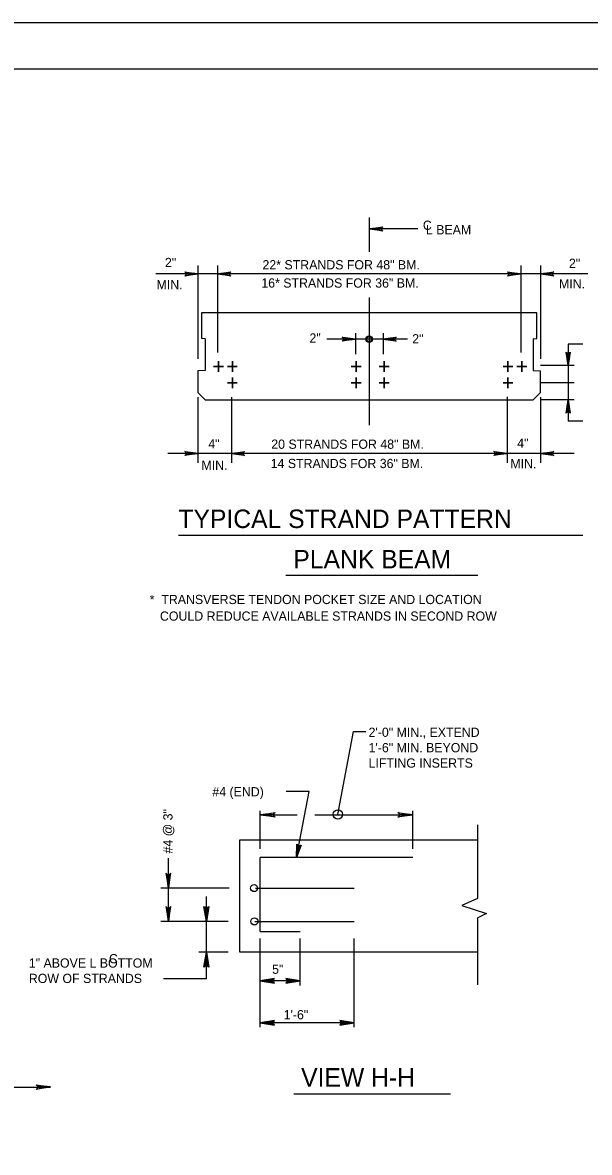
# Model space of a CAD drawing. Extents: x 639331 to 643089, y 299088 to 300975.
# Drawn here: x 642553.9 to 642738.1, y 300502.8 to 300869.7 of the extents above; entities that cross this region are included whole.
import ezdxf

# ---------------------------------------------------------------- set-up
doc = ezdxf.new("R2010")
doc.units = 0
doc.layers.add('1', color=7, linetype='Continuous')
doc.layers.add('PLT-BNDY', color=7, linetype='Continuous')

msp = doc.modelspace()

# ---------------------------------------------------------------- linework, layer by layer
at = {"layer": '1'}
for p, q in [((642274.06, 300854.66), (643060.06, 300854.66)), ((642666.55, 300806.4), (642666.55, 300795.18)), ((642682.33, 300802.64), (642666.7, 300802.64)), ((642617.31, 300788.03), (642597.21, 300788.03)), ((642610.9, 300790.75), (642610.9, 300760.45)), ((642617.31, 300790.75), (642617.31, 300762.54)), ((642715.79, 300788.03), (642617.31, 300788.03)), ((642715.79, 300790.75), (642715.79, 300762.54)), ((642737.64, 300788.03), (642715.79, 300788.03)), ((642722.2, 300790.75), (642722.2, 300760.45)), ((642666.55, 300780.44), (642666.55, 300738.9)), ((642721, 300775.37), (642612.1, 300775.37)), ((642612.1, 300775.37), (642612.1, 300767.13)), ((642721, 300767.13), (642721, 300775.37)), ((642613.3, 300766.98), (642612.1, 300767.13)), ((642613.3, 300766.98), (642613.3, 300756.71)), ((642662.05, 300766.87), (642652.84, 300766.87)), ((642662.05, 300768.85), (642662.05, 300761.94)), ((642671.05, 300766.87), (642662.05, 300766.87)), ((642671.05, 300768.85), (642671.05, 300761.94)), ((642679.04, 300766.87), (642671.05, 300766.87)), ((642719.8, 300766.98), (642721, 300767.13)), ((642719.8, 300766.98), (642719.8, 300756.71)), ((642731.21, 300765.26), (642731.21, 300758.34)), ((642735.94, 300765.26), (642731.21, 300765.26)), ((642733.19, 300758.34), (642722.2, 300758.34)), ((642731.21, 300758.34), (642731.21, 300747.17)), ((642613.3, 300756.71), (642610.9, 300756.56)), ((642610.9, 300756.56), (642610.9, 300749.57)), ((642719.8, 300756.71), (642722.2, 300756.56)), ((642722.2, 300749.57), (642722.2, 300756.56)), ((642733.19, 300752.64), (642722.2, 300752.64)), ((642610.9, 300749.57), (642613.3, 300747.17)), ((642610.9, 300748.01), (642610.9, 300726.66)), ((642621.76, 300748.01), (642621.76, 300726.66)), ((642711.34, 300748.13), (642711.34, 300726.66)), ((642722.2, 300749.57), (642719.8, 300747.17)), ((642722.2, 300748.01), (642722.2, 300726.66)), ((642613.3, 300747.17), (642719.8, 300747.17)), ((642733.19, 300747.17), (642722.2, 300747.17)), ((642731.21, 300747.17), (642731.21, 300740.27)), ((642735.94, 300740.27), (642731.21, 300740.27)), ((642610.9, 300729.74), (642601.17, 300729.74)), ((642722.2, 300729.74), (642610.9, 300729.74)), ((642733.19, 300729.74), (642722.2, 300729.74)), ((642604.6, 300703.23), (642736, 300703.23)), ((642639.5, 300690.22), (642701.81, 300690.22)), ((642656.39, 300612.54), (642661.47, 300639.46)), ((642661.47, 300639.46), (642665.42, 300639.46)), ((642647, 300619.94), (642639.58, 300619.94)), ((642642.96, 300598.5), (642647, 300619.94)), ((642631.13, 300612.39), (642643.11, 300612.39)), ((642648.88, 300612.39), (642680.75, 300612.39)), ((642701.75, 300609.14), (642701.75, 300585.26)), ((642624.56, 300604.28), (642701.75, 300604.28)), ((642624.56, 300567.8), (642624.56, 300604.28)), ((642631.13, 300574.54), (642631.13, 300598.5)), ((642621.04, 300588.62), (642598.8, 300588.62)), ((642701.75, 300578.89), (642701.75, 300557.25)), ((642620.75, 300577.8), (642598.8, 300577.8)), ((642620.75, 300567.8), (642611.15, 300567.8)), ((642701.75, 300567.8), (642624.56, 300567.8)), ((642613.65, 300559.15), (642599.71, 300559.15)), ((642562.98, 300523.85), (642550.24, 300523.85)), ((642642.01, 300521.83), (642693.01, 300521.83))]:
    msp.add_line(p, q, dxfattribs=at)
for points in [[(642670.78, 300802.12), (642670.63, 300802.42), (642666.7, 300802.64), (642670.78, 300802.12), (642670.99, 300801.94), (642666.7, 300802.64), (642670.63, 300802.83), (642670.77, 300803.12), (642666.7, 300802.64), (642670.99, 300803.32), (642670.77, 300803.12)], [(642606.81, 300788.54), (642606.96, 300788.24), (642610.9, 300788.03), (642606.81, 300788.54), (642606.6, 300788.72), (642610.9, 300788.03), (642606.97, 300787.83), (642606.82, 300787.54), (642610.9, 300788.03), (642606.6, 300787.34), (642606.82, 300787.54)], [(642621.4, 300787.51), (642621.24, 300787.81), (642617.31, 300788.03), (642621.4, 300787.51), (642621.6, 300787.33), (642617.31, 300788.03), (642621.24, 300788.22), (642621.38, 300788.51), (642617.31, 300788.03), (642621.6, 300788.71), (642621.38, 300788.51)], [(642711.7, 300788.54), (642711.86, 300788.24), (642715.79, 300788.03), (642711.7, 300788.54), (642711.49, 300788.72), (642715.79, 300788.03), (642711.86, 300787.83), (642711.71, 300787.54), (642715.79, 300788.03), (642711.49, 300787.34), (642711.71, 300787.54)], [(642726.29, 300787.51), (642726.13, 300787.81), (642722.2, 300788.03), (642726.29, 300787.51), (642726.5, 300787.33), (642722.2, 300788.03), (642726.13, 300788.22), (642726.27, 300788.51), (642722.2, 300788.03), (642726.5, 300788.71), (642726.27, 300788.51)], [(642657.96, 300767.39), (642658.11, 300767.09), (642662.05, 300766.87), (642657.96, 300767.39), (642657.75, 300767.56), (642662.05, 300766.87), (642658.11, 300766.68), (642657.97, 300766.39), (642662.05, 300766.87), (642657.75, 300766.19), (642657.97, 300766.39)], [(642675.14, 300766.36), (642674.99, 300766.66), (642671.05, 300766.87), (642675.14, 300766.36), (642675.35, 300766.18), (642671.05, 300766.87), (642674.98, 300767.07), (642675.13, 300767.36), (642671.05, 300766.87), (642675.35, 300767.56), (642675.13, 300767.36)], [(642731.72, 300762.42), (642731.43, 300762.27), (642731.21, 300758.34), (642731.72, 300762.42), (642731.9, 300762.63), (642731.21, 300758.34), (642731.01, 300762.27), (642730.72, 300762.41), (642731.21, 300758.34), (642730.53, 300762.63), (642730.72, 300762.41)], [(642730.7, 300743.08), (642730.99, 300743.23), (642731.21, 300747.17), (642730.7, 300743.08), (642730.52, 300742.87), (642731.21, 300747.17), (642731.4, 300743.24), (642731.7, 300743.09), (642731.21, 300747.17), (642731.89, 300742.87), (642731.7, 300743.09)], [(642606.81, 300730.25), (642606.96, 300729.95), (642610.9, 300729.74), (642606.81, 300730.25), (642606.6, 300730.43), (642610.9, 300729.74), (642606.97, 300729.54), (642606.82, 300729.25), (642610.9, 300729.74), (642606.6, 300729.05), (642606.82, 300729.25)], [(642625.84, 300729.22), (642625.69, 300729.52), (642621.76, 300729.74), (642625.84, 300729.22), (642626.05, 300729.04), (642621.76, 300729.74), (642625.69, 300729.93), (642625.83, 300730.22), (642621.76, 300729.74), (642626.05, 300730.42), (642625.83, 300730.22)], [(642707.25, 300730.25), (642707.41, 300729.95), (642711.34, 300729.74), (642707.25, 300730.25), (642707.04, 300730.43), (642711.34, 300729.74), (642707.41, 300729.54), (642707.27, 300729.25), (642711.34, 300729.74), (642707.04, 300729.05), (642707.27, 300729.25)], [(642726.29, 300729.22), (642726.13, 300729.52), (642722.2, 300729.74), (642726.29, 300729.22), (642726.5, 300729.04), (642722.2, 300729.74), (642726.13, 300729.93), (642726.27, 300730.22), (642722.2, 300729.74), (642726.5, 300730.42), (642726.27, 300730.22)], [(642631.13, 300601.39), (642631.13, 300613.7)], [(642635.74, 300611.81), (642635.57, 300612.15), (642631.13, 300612.39), (642635.74, 300611.81), (642635.98, 300611.61), (642631.13, 300612.39), (642635.56, 300612.61), (642635.73, 300612.94), (642631.13, 300612.39), (642635.98, 300613.16), (642635.73, 300612.94)], [(642676.14, 300612.97), (642676.31, 300612.64), (642680.75, 300612.39), (642676.14, 300612.97), (642675.9, 300613.18), (642680.75, 300612.39), (642676.31, 300612.17), (642676.15, 300611.84), (642680.75, 300612.39), (642675.9, 300611.62), (642676.15, 300611.84)], [(642680.75, 300601.39), (642680.75, 300613.7)], [(642644.22, 300602.42), (642643.9, 300602.32), (642642.96, 300598.5), (642644.22, 300602.42), (642644.43, 300602.59), (642642.96, 300598.5), (642643.49, 300602.4), (642643.23, 300602.59), (642642.96, 300598.5), (642643.08, 300602.84), (642643.23, 300602.59)], [(642601.29, 300577.8), (642601.29, 300598.34)], [(642680.75, 300598.5), (642631.13, 300598.5)], [(642600.71, 300593.24), (642601.04, 300593.06), (642601.29, 300588.62), (642600.71, 300593.24), (642600.51, 300593.47), (642601.29, 300588.62), (642601.51, 300593.06), (642601.84, 300593.22), (642601.29, 300588.62), (642602.06, 300593.47), (642601.84, 300593.22)], [(642613.65, 300577.8), (642613.65, 300585.84)], [(642629.62, 300588.62), (642661.69, 300588.62)], [(642600.71, 300582.42), (642601.04, 300582.24), (642601.29, 300577.8), (642600.71, 300582.42), (642600.51, 300582.65), (642601.29, 300577.8), (642601.51, 300582.24), (642601.84, 300582.4), (642601.29, 300577.8), (642602.06, 300582.65), (642601.84, 300582.4)], [(642614.22, 300582.42), (642613.89, 300582.24), (642613.65, 300577.8), (642614.22, 300582.42), (642614.43, 300582.65), (642613.65, 300577.8), (642613.43, 300582.24), (642613.1, 300582.4), (642613.65, 300577.8), (642612.87, 300582.65), (642613.1, 300582.4)], [(642701.75, 300585.26), (642696.63, 300583.01), (642704.63, 300580.39), (642701.63, 300578.89)], [(642613.65, 300559.15), (642613.65, 300577.8)], [(642629.36, 300577.8), (642661.69, 300577.8)], [(642631.13, 300574.54), (642644.12, 300574.54)], [(642631.13, 300543.46), (642631.13, 300572.3)], [(642644.12, 300556.96), (642644.12, 300572.3)], [(642661.69, 300543.46), (642661.69, 300572.3)], [(642613.07, 300563.19), (642613.4, 300563.36), (642613.65, 300567.8), (642613.07, 300563.19), (642612.86, 300562.95), (642613.65, 300567.8), (642613.86, 300563.36), (642614.2, 300563.2), (642613.65, 300567.8), (642614.42, 300562.95), (642614.2, 300563.2)], [(642635.6, 300559.1), (642635.43, 300558.78), (642631.13, 300558.54), (642635.6, 300559.1), (642635.83, 300559.3), (642631.13, 300558.54), (642635.43, 300558.33), (642635.58, 300558.01), (642631.13, 300558.54), (642635.83, 300557.79), (642635.58, 300558.01)], [(642635.6, 300559.1), (642635.43, 300558.78), (642631.13, 300558.54), (642635.6, 300559.1), (642635.83, 300559.3), (642631.13, 300558.54), (642635.43, 300558.33), (642635.58, 300558.01), (642631.13, 300558.54), (642635.83, 300557.79), (642635.58, 300558.01)], [(642644.12, 300558.54), (642631.13, 300558.54)], [(642639.65, 300557.98), (642639.82, 300558.3), (642644.12, 300558.54), (642639.65, 300557.98), (642639.42, 300557.78), (642644.12, 300558.54), (642639.82, 300558.75), (642639.66, 300559.07), (642644.12, 300558.54), (642639.42, 300559.28), (642639.66, 300559.07)], [(642635.6, 300545.44), (642635.43, 300545.12), (642631.13, 300544.88), (642635.6, 300545.44), (642635.83, 300545.63), (642631.13, 300544.88), (642635.43, 300544.67), (642635.58, 300544.35), (642631.13, 300544.88), (642635.83, 300544.13), (642635.58, 300544.35)], [(642657.22, 300544.32), (642657.39, 300544.64), (642661.69, 300544.88), (642657.22, 300544.32), (642656.99, 300544.12), (642661.69, 300544.88), (642657.39, 300545.09), (642657.23, 300545.41), (642661.69, 300544.88), (642656.99, 300545.62), (642657.23, 300545.41)], [(642661.69, 300544.88), (642631.13, 300544.88)], [(642558.6, 300524.47), (642558.8, 300524.27), (642562.98, 300524.06), (642558.6, 300524.47), (642558.39, 300524.68), (642562.98, 300524.06), (642558.8, 300523.85), (642558.6, 300523.43), (642562.98, 300524.06), (642558.39, 300523.22), (642558.6, 300523.43)]]:
    msp.add_lwpolyline(points, dxfattribs=at)
for centre, radius in [((642666.57, 300766.86), 1.06), ((642666.57, 300766.86), 0.831), ((642656.39, 300612.54), 1.52), ((642629.14, 300588.62), 1.15), ((642629.27, 300577.8), 1.15)]:
    msp.add_circle(centre, radius, dxfattribs=at)
at = {"layer": 'PLT-BNDY'}
msp.add_lwpolyline([(642234.06, 300869.66), (643075.06, 300869.66), (643075.06, 300275.66), (642234.06, 300275.66)], close=True, dxfattribs=at)

# ---------------------------------------------------------------- texts
at = {"layer": '1'}
for s, height, p in [('C', 3, (642683.99, 300802.36)), ('L BEAM', 3, (642684.98, 300800.9)), ('2"', 3, (642600.18, 300790.26)), ('22* STRANDS FOR 48" BM.', 3, (642631.88, 300789.52)), ('2"', 3, (642731.46, 300790.01)), ('MIN.', 3, (642597.46, 300783.08)), ('16* STRANDS FOR 36" BM.', 3, (642631.5, 300783.6)), ('MIN.', 3, (642728.24, 300783.33)), ('2"', 3, (642647.15, 300765.73)), ('2"', 3, (642680.53, 300765.48)), ('+', 5.04, (642615.62, 300755.56)), ('+', 5.04, (642620.15, 300755.56)), ('+', 5.04, (642660.36, 300755.56)), ('+', 5.04, (642669.45, 300755.56)), ('+', 5.04, (642709.65, 300755.56)), ('+', 5.04, (642714.18, 300755.56)), ('+', 5.04, (642620.15, 300750.26)), ('+', 5.04, (642660.36, 300750.26)), ('+', 5.04, (642669.45, 300750.26)), ('+', 5.04, (642709.65, 300750.26)), ('4"', 3, (642614.27, 300731.36)), ('20 STRANDS FOR 48" BM.', 3, (642634.73, 300731.26)), ('4"', 3, (642714.64, 300731.6)), ('MIN.', 3, (642612.04, 300724.43)), ('14 STRANDS FOR 36" BM.', 3, (642634.54, 300725)), ('MIN.', 3, (642712.42, 300724.92)), ('TYPICAL STRAND PATTERN', 6, (642604.55, 300705.54)), ('PLANK BEAM', 6, (642641.91, 300692.42)), ('*  TRANSVERSE TENDON POCKET SIZE AND LOCATION', 3, (642595.22, 300680.84)), ('   COULD REDUCE AVAILABLE STRANDS IN SECOND ROW', 3, (642595.22, 300675.44)), ('2\'-0" MIN., EXTEND', 3, (642666.35, 300637.72)), ('1\'-6" MIN. BEYOND', 3, (642666.35, 300632.72)), ('LIFTING INSERTS', 3, (642666.35, 300627.72)), ('#4 (END)', 3, (642615.59, 300618.4)), ('1" ABOVE L BOTTOM', 3, (642555.96, 300562.79)), ('C', 3, (642582, 300564.19)), ('ROW OF STRANDS', 3, (642555.96, 300557.79)), ('5"', 3, (642635, 300560.78)), ('1\'-6"', 3, (642638.76, 300546.01)), ('VIEW H-H', 6, (642644.43, 300524.15))]:
    msp.add_text(s, height=height, dxfattribs=at).set_placement(p)
msp.add_text('#4 @ 3"', height=3, rotation=90, dxfattribs=at).set_placement((642602.64, 300599.84))

doc.saveas('drawing.dxf')
